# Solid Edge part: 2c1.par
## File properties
Author: edge
Template: jis part.par
Last saved by: edge
Revision: 8
Application: Solid Edge
文書内容のタイプ: 0
Accuracy: 0.990
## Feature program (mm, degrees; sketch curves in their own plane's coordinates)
sketch for "unnamed RevolvedProtrusion 1" plane through (0, 0, 0) normal (0, -1, 0) x-axis (1, 0, 0)
  line (-25, 20) -> (25, 20)
  line (25, 20) -> (25, 22.5)
  line (25, 22.5) -> (35, 22.5)
  line (35, 22.5) -> (35, 20)
  line (35, 20) -> (150, 20)
  line (150, 20) -> (150, 0)
  line (150, 0) -> (-150, 0)
  line (-150, 0) -> (-150, 20)
  line (-150, 20) -> (-27, 20)
  line (-27, 20) -> (-27, 19)
  line (-27, 19) -> (-25, 19)
  line (-25, 19) -> (-25, 20)
revolve "unnamed RevolvedProtrusion 1" add finite 360 deg
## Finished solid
Body 1: solid body, 11 faces, 10 edges, 0 vertices.
  Faces by surface: plane 6, cylinder 5
  Edges by curve: circle 10
Bounding box of the edges (mm): 300.000 x 45.000 x 45.000, from (-150, -22.5, -22.5) to (150, 22.5, 22.5).
Cylindrical faces by radius (mm): R19 x1, R20 x3, R22.5 x1
Planar faces by outward normal: +x 3, -x 3
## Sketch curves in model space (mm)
line (-150, 0, 20) -> (-27, 0, 20)
line (-27, 0, 20) -> (-27, 0, 19)
line (-27, 0, 19) -> (-25, 0, 19)
line (-25, 0, 19) -> (-25, 0, 20)
line (-25, 0, 20) -> (25, 0, 20)
line (25, 0, 20) -> (25, 0, 22.5)
line (25, 0, 22.5) -> (35, 0, 22.5)
line (35, 0, 22.5) -> (35, 0, 20)
line (35, 0, 20) -> (150, 0, 20)
line (150, 0, 20) -> (150, 0, 0)
line (150, 0, 0) -> (-150, 0, 0)
line (-150, 0, 0) -> (-150, 0, 20)
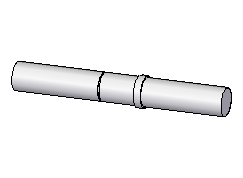
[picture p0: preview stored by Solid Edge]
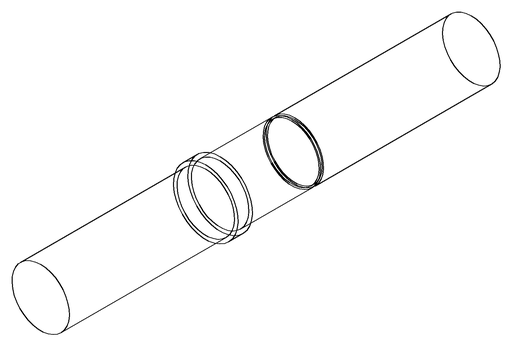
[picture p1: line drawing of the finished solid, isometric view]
